// TIA Portal project "SPS-CLOCK" (V15)

(* hardware
DEVICE "SIMATIC 300-Station(2)"  S7-300 station
   slot 0: "Rack 0"  Rail  6ES7 390-1***0-0AA0
   slot 2: "CPU314(1)"  Unspecific CPU S7 300  6ES7 3XX-XXXXX-XXXX
*)

// ===== PLC "CPU314(1)"  Unspecific CPU S7 300 =====

VAR_GLOBAL   // PLC tag table "Standard-Variablentabelle"
   "Tag_1" AT %MB200 : Byte;
   "Tag_2" AT %MB201 : Byte;
   "Tag_3" AT %IB0 : Byte;
   "Tag_4" AT %T90 : Timer;
   "Tag_5" AT %T91 : Timer;
   "Tag_6" AT %QB4 : Byte;
END_VAR

DATA_BLOCK "DB99"   // DB99
{ S7_Optimized_Access := 'FALSE' }
NAME : SPS_CLOC
VERSION : 0.1
"FB99"
BEGIN
END_DATA_BLOCK

FUNCTION_BLOCK "FB99"   // FB99, STL
TITLE = SPS-Clock
{ S7_Optimized_Access := 'FALSE' }
VERSION : 0.0
   VAR_INPUT
      TD : Timer;
      "TO" : Timer;
   END_VAR
   VAR
      SCHRITTKETTE : Byte;
      REGISTER : Byte;
      LEER6 : Byte;
      LEER7 : Byte;
      LEER8 : Byte;
      IN_STATUSBITS : Byte;
      IN_SEKUNDEN : Byte;
      IN_MINUTEN : Byte;
      IN_STUNDEN : Byte;
      IN_TAGE : Byte;
      IN_MONATE : Byte;
      IN_JAHRE : Byte;
      IN_WT_LS : Byte;
      LEER17 : Byte;
      LEER18 : Byte;
      HR_STATUSBITS : Byte;
      HR_SEKUNDEN : Byte;
      HR_MINUTEN : Byte;
      HR_STUNDEN : Byte;
      HR_TAGE : Byte;
      HR_MONATE : Byte;
      HR_JAHRE : Byte;
      HR_WT_LS : Byte;
      LEER27 : Byte;
      LEER28 : Byte;
      OUT_STATUSBITS : Byte;
      OUT_SEKUNDEN : Byte;
      OUT_MINUTEN : Byte;
      OUT_STUNDEN : Byte;
      OUT_TAGE : Byte;
      OUT_MONATE : Byte;
      OUT_JAHRE : Byte;
      OUT_WOCHENTAG : Byte;
      OUT_LAST_SYNC : Byte;
   END_VAR
   VAR_TEMP
      VKE0 : Bool;
      NULL : Bool;
      FEHLER : Bool;
      PARITY : Bool;
      C_BIT : Bool;
      SCHIEBEREGISTER : Word;
      VEKTOR : DWord;
   END_VAR
BEGIN

REGION Network 1: Grunddaten übernehmen
         L     "Tag_1";
         L     16#001F;  // - Nicht für SPS-Clock verwendete Signale ausblenden
         AW;
         T     "Tag_1";
         A     #VKE0;
         R     #VKE0;  // - VKE 0 Bit erzeugen
END_REGION

REGION Network 2: "Null" und "Fehler"-Signal Auswertung
         L     16#0000;
         L     "Tag_1";
         ==I;
         =     #NULL;  // - Null-Signal
         L     16#000F;
         ==I;
         =     #FEHLER;  // - Fehler-Signal
END_REGION

REGION Network 3: Schritt 0 / "0" Ausgeben
         L     #SCHRITTKETTE;
         L     16#0000;
         <>I;
         JC    M001;
         T     "Tag_2";  // - Ausgabe "0"
         L     "Tag_1";
         L     16#0000;  // - Wenn "Null" als
         <>I;  //   Anwort dann nächster Schritt
         JC    M001;
         A     #VKE0;
         SD    #TD;  // - Timer reset
         L     16#0001;
         T     #SCHRITTKETTE;  // - nächster Schritt
   M001: NOP   0;
END_REGION

REGION Network 4: Schritt 1 / "Register" Ausgeben
         L     #SCHRITTKETTE;
         L     16#0001;
         <>I;
         JC    M002;
         L     #REGISTER;  // - Ausgabe Register
         T     "Tag_2";
         L     S5T#100MS;
         SD    #TD;
         AN    #TD;  // - wenn Timer abgelaufen
         JC    M002;  //   dann weitere Prüfung
         R     #PARITY;  // - zu Beginn Parity-Bit
         L     "Tag_1";  //   rücksetzen und Eingangsdaten
         L     16#2000;  //   temporär übernehmen
         OW;  //   und Kennbit setzen
         T     #SCHIEBEREGISTER;
   M004: AN    <??.?>;
         JC    M003;
         AN    #PARITY;  // - Parity in abhängigkeit
         =     #PARITY;  //   vom Datenbit toggeln
   M003: L     #SCHIEBEREGISTER;
         SRW   1;
         T     #SCHIEBEREGISTER;
         AN    <??.?>;  // - wenn nicht fertig
         JC    M004;  //   dann Schleife
         AN    #PARITY;  // - Prüfen ob Parity O.K.
         JC    M005;  //   und wenn Nein dann Ende
         L     #REGISTER;  // - Registervektor laden
         SRW   1;  //   durch 2 Teilen
         INC   9;  //   um 9 erhöhen
         SLD   3;  //   und als Vektor ablegen
         T     #VEKTOR;
         A     %XData5.0;  // welche Tetrade ?
         JC    M006;
         L     DIB[ #VEKTOR];  // - Low Tetrade eintragen
         L     16#00F0;
         AW;
         L     "Tag_1";
         SLW   12;
         SRW   12;
         OW;
         T     DIB[ #VEKTOR];
         JU    M005;
   M006: L     DIB[ #VEKTOR];  // - High Tetrade eintragen
         L     16#000F;
         AW;
         L     "Tag_1";
         SLW   12;
         SRW   8;
         OW;
         T     DIB[ #VEKTOR];
   M005: L     #REGISTER;  // - nächstes Register
         INC   1;
         T     #REGISTER;
         L     16#0000;  // - zurück zu Schritt 1
         T     #SCHRITTKETTE;
   M002: NOP   0;
END_REGION

REGION Network 5: Registeruebernahme
         L     #REGISTER;
         L     16;
         <I;
         JC    M007;
         L     1;  // - Registerzyklus auf 1 setzen
         T     #REGISTER;
         R     #C_BIT;  // - Kontrollbit rücksetzen
         L     #IN_MINUTEN;  // -> Prüfung der einzelnen Register
         L     #HR_MINUTEN;  //    - Minuten
         <>I;
         S     #C_BIT;
         L     #IN_STUNDEN;  //    - Stunden
         L     #HR_STUNDEN;
         <>I;
         S     #C_BIT;
         L     #IN_TAGE;  //    - Tage
         L     #HR_TAGE;
         <>I;
         S     #C_BIT;
         L     #IN_MONATE;  //    - Monate
         L     #HR_MONATE;
         <>I;
         S     #C_BIT;
         L     #IN_JAHRE;  //    - Jahre
         L     #HR_JAHRE;
         <>I;
         S     #C_BIT;
         L     #IN_WT_LS;  //    - Wochentage und Synchronisation
         L     #HR_WT_LS;
         <>I;
         S     #C_BIT;
         L     #IN_STATUSBITS;  // - Daten ins Hilfsregister
         T     #HR_STATUSBITS;  //   übernehmen
         L     #IN_SEKUNDEN;
         T     #HR_SEKUNDEN;
         L     #IN_MINUTEN;
         T     #HR_MINUTEN;
         L     #IN_STUNDEN;
         T     #HR_STUNDEN;
         L     #IN_TAGE;
         T     #HR_TAGE;
         L     #IN_MONATE;
         T     #HR_MONATE;
         L     #IN_JAHRE;
         T     #HR_JAHRE;
         L     #IN_WT_LS;
         T     #HR_WT_LS;
         A     #C_BIT;
         JC    M007;
         L     #IN_STATUSBITS;  // - Nur wenn Fehlerbit nicht
         SRW   4;  //   gesetzt, werden die Daten
         T     #OUT_STATUSBITS;  //   ins Ausgaberegister übernommen
         L     #IN_SEKUNDEN;
         T     #OUT_SEKUNDEN;
         L     #IN_MINUTEN;
         T     #OUT_MINUTEN;
         L     #IN_STUNDEN;
         T     #OUT_STUNDEN;
         L     #IN_TAGE;
         T     #OUT_TAGE;
         L     #IN_MONATE;
         T     #OUT_MONATE;
         L     #IN_JAHRE;
         T     #OUT_JAHRE;
         L     #IN_WT_LS;
         L     16#000F;
         AW;
         T     #OUT_WOCHENTAG;
         L     #IN_WT_LS;
         L     16#00F0;
         AW;
         SRW   4;
         T     #OUT_LAST_SYNC;
   M007: NOP   0;
END_REGION

REGION Network 6: Minimumkontrolle
         L     #VEKTOR;
         L     0;
         >I;
         JC    M008;
         L     1;
         T     #VEKTOR;
   M008: NOP   0;
         BE;
END_REGION
END_FUNCTION_BLOCK

FUNCTION "FC1" : Void   // FC1, STL
{ S7_Optimized_Access := 'FALSE' }
VERSION : 0.0
BEGIN

REGION Network 1: Aufruf des SPS-Clock Funktionsbausteines mit Parameterübergabe
         L     "Tag_3";  // - Eingaenge von SPS-CLOCK
         T     "Tag_1";  // in SME

         CALL  "FB99", "DB99"
         ( TD   := "Tag_4",
           "TO" := "Tag_5"
         );

         L     "Tag_6";
         L     16#00E0;
         AW;
         L     "Tag_2";
         OW;
         T     "Tag_6";
         BE;
END_REGION
END_FUNCTION

ORGANIZATION_BLOCK "OB1"   // OB1, STL
{ S7_Optimized_Access := 'FALSE' }
AUTHOR : AKO
FAMILY : Master
NAME : Master
VERSION : 0.1
   VAR_TEMP
      OB1_EV_CLASS : Byte;   // Bits 0-3 = 1 (Coming event), Bits 4-7 = 1 (Event class 1)
      OB1_SCAN_1 : Byte;   // 1 (Cold restart scan 1 of OB 1), 3 (Scan 2-n of OB 1)
      OB1_PRIORITY : Byte;   // 1 (Priority of 1 is lowest)
      OB1_OB_NUMBR : Byte;   // 1 (Organization block 1, OB1)
      OB1_RESERVED_1 : Byte;   // Reserved for system
      OB1_RESERVED_2 : Byte;   // Reserved for system
      OB1_PREV_CYCLE : Int;   // Cycle time of previous OB1 scan (milliseconds)
      OB1_MIN_CYCLE : Int;   // Minimum cycle time of OB1 (milliseconds)
      OB1_MAX_CYCLE : Int;   // Maximum cycle time of OB1 (milliseconds)
      OB1_DATE_TIME : Date_And_Time;   // Date and time OB1 started
   END_VAR
BEGIN

REGION Network 1: Aufruf des Masterprogrammbausteins
         CALL  "FC1";
         BE;
END_REGION
END_ORGANIZATION_BLOCK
